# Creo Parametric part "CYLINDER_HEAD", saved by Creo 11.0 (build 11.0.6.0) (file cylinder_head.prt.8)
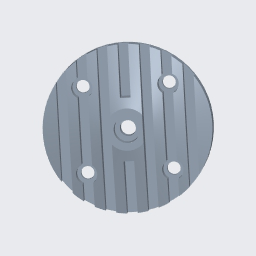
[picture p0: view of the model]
Materials in the file: 10038_S235JR

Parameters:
  MATERIAL = "10038_S235JR"
  PTC_MATERIAL_NAME = "10038_S235JR"
  PTC_MASTER_MATERIAL = "10038_S235JR"
  SELECT_EN_NAME = "S235JR"
  SELECT_DIN_NAME = "RSt37-2"
  SELECT_MATERIAL_NUMBER = "1.0038"
  SELECT_ASTM_NAME = "A 283 M Grade 2"
  MATERIAL_GROUP = "ME_ST_Baustahl"
  STANDARD_EN_DELIVERYSPEC = "DIN EN 10025-2"
  STANDARD_DIN_DELIVERYSPEC = "DIN EN 10025-2"

Other parameters: GEWICHT

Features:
  1. datum plane "RIGHT"
  2. datum plane "TOP"
  3. datum plane "FRONT"
  4. coordinate system
  5. datum axis
  6. datum axis
  7. datum axis
  8. protrusion
  9. cut
  10. cut
  11. datum plane "DTM1"
  12. cut
  13. mirror "Mirror 10"
  14. extruded cut "Extrude 9 (2)"
  15. extrusion "Extrude 10"
  16. hole "Hole 1"
  17. hole "Hole 2"
  18. hole "Hole 3"
  19. pattern "Pattern 1"
  20. extruded cut "Extrude 11"
  21. extruded cut "Extrude 11 [2]"
  22. extruded cut "Extrude 11 [3]"
  23. mirror "Mirror 11"
  24. pattern "Pattern 1 (2)"
  25. extruded cut "Extrude 11 (2) [1]"
  26. extruded cut "Extrude 11 (2) [2]"
  27. extruded cut "Extrude 11 (2) [3]"
  28. mirror "Mirror 12"
  29. hole "Hole 2 (2)"
  30. mirror "Mirror 13"
  31. hole "Hole 3 (2)"
  32. mirror "Mirror 14"
  33. hole "Hole 3 (3)"
  34. mirror "Mirror 15"
  35. hole "Hole 2 (3)"
  36. mirror "Mirror 16"
  37. hole "Hole 2 (4)"
  38. mirror "Mirror 17"
  39. hole "Hole 3 (4)"

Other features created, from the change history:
  extruded cut "Extrude 9"
  extruded cut "Extrude 1 [4]"
  extruded cut "Extrude 6 [4]"
  extruded cut "Extrude 7 [4]"
  extruded cut "Extrude 8 [4]"
  mirror "Mirror 11"
  extruded cut "Extrude 11 (2)"

Other named items: A_Y, A_X, A_Z, CS0

Layers: BEZUGSACHSEN, BEZUGSEBENEN, BOHRUNGEN

Surfaces: 30 plane, 9 cylinder, 2 cone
